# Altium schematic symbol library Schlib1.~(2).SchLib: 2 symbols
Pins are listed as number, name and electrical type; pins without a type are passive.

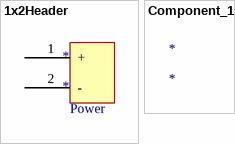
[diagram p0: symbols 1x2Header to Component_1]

## 1x2Header
designator *
pins: 1 +, 2 -

## Component_1
designator *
